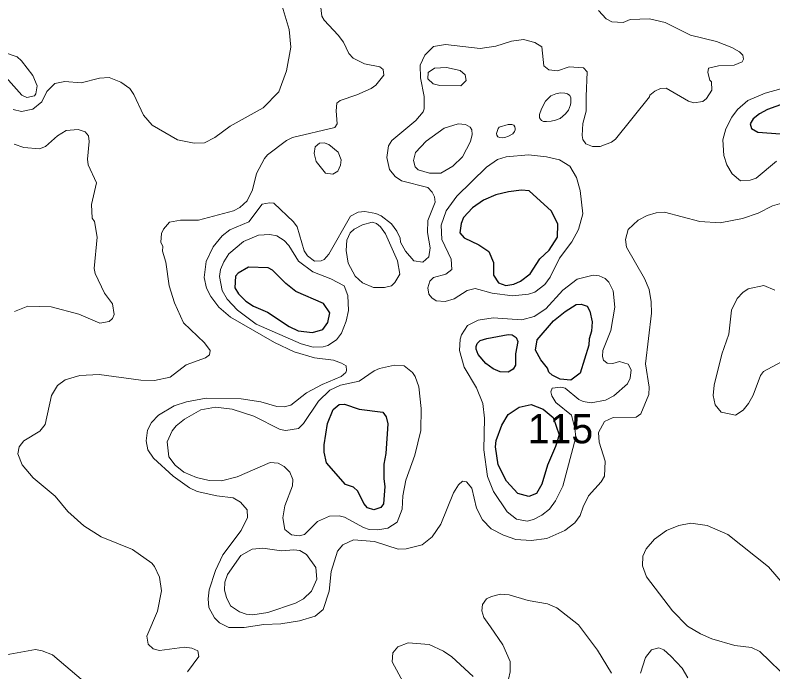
# Model space of a CAD drawing. Extents: x 673.6 to 698.9, y 7012 to 7040.1.
# Drawn here: x 682.608 to 684.675, y 7029.641 to 7031.434 of the extents above; entities that cross this region are included whole.
import ezdxf

# ---------------------------------------------------------------- set-up
doc = ezdxf.new("R2010")
doc.units = 0
doc.header["$LTSCALE"] = 0.032
doc.layers.add('1', color=7, linetype='Continuous', lineweight=25)
doc.layers.add('2', color=7, linetype='Continuous', lineweight=13)
doc.layers.add('21', color=7, linetype='Continuous')

msp = doc.modelspace()

# ---------------------------------------------------------------- linework, layer by layer
at = {"layer": '1'}
msp.add_lwpolyline([(684.7869, 7031.2225), (684.6612, 7031.1768), (684.6387, 7031.1647), (684.6215, 7031.1512), (684.6137, 7031.1377), (684.6176, 7031.1249), (684.6346, 7031.1151), (684.7212, 7031.109)], dxfattribs=at)
for points in [[(684.071, 7030.8996), (684.0106, 7030.9552), (683.9898, 7030.9562), (683.9537, 7030.9521), (683.9195, 7030.9439), (683.886, 7030.9297), (683.8561, 7030.908), (683.8311, 7030.8818), (683.8246, 7030.8655), (683.8215, 7030.8404), (683.8328, 7030.8268), (683.8731, 7030.8074), (683.9003, 7030.7892), (683.9132, 7030.7594), (683.9136, 7030.7241), (683.9265, 7030.7039), (683.947, 7030.6966), (683.9687, 7030.6995), (683.9872, 7030.7085), (684.0136, 7030.7278), (684.0395, 7030.7688), (684.0652, 7030.7924), (684.0876, 7030.828), (684.0885, 7030.8633)], [(683.374, 7030.6801), (683.3465, 7030.7013), (683.3102, 7030.7384), (683.2987, 7030.7449), (683.2443, 7030.7467), (683.2163, 7030.7303), (683.2091, 7030.7216), (683.2078, 7030.6896), (683.2171, 7030.6737), (683.2372, 7030.6535), (683.2583, 7030.6399), (683.2967, 7030.6232), (683.3556, 7030.5841), (683.38, 7030.5728), (683.4191, 7030.5676), (683.4471, 7030.5765), (683.4615, 7030.595), (683.4663, 7030.6217), (683.4491, 7030.6467)], [(684.1743, 7030.5505), (684.1735, 7030.5335), (684.1498, 7030.4569), (684.1242, 7030.4377), (684.095, 7030.441), (684.0729, 7030.4517), (684.0646, 7030.4594), (684.0606, 7030.4702), (684.0421, 7030.4937), (684.0278, 7030.5196), (684.0325, 7030.5482), (684.0773, 7030.5998), (684.1088, 7030.6255), (684.1385, 7030.644), (684.1525, 7030.6454), (684.1689, 7030.6403), (684.1763, 7030.6258), (684.1828, 7030.597), (684.1804, 7030.5716)], [(683.9535, 7030.4594), (683.9317, 7030.4605), (683.9123, 7030.4692), (683.8923, 7030.4835), (683.8717, 7030.5081), (683.8658, 7030.5226), (683.8661, 7030.5297), (683.8686, 7030.5377), (683.8771, 7030.5458), (683.8949, 7030.5512), (683.9535, 7030.5626), (683.9641, 7030.5616), (683.9746, 7030.5541), (683.9799, 7030.5433), (683.9736, 7030.5099), (683.973, 7030.4792), (683.9668, 7030.4677)], [(683.6197, 7030.2377), (683.6143, 7030.2088), (683.6135, 7030.1686), (683.6167, 7030.1476), (683.6132, 7030.1005), (683.6054, 7030.0906), (683.5871, 7030.084), (683.5697, 7030.0895), (683.5592, 7030.1009), (683.5432, 7030.1352), (683.5308, 7030.1454), (683.5095, 7030.1528), (683.4576, 7030.2122), (683.4508, 7030.2409), (683.4509, 7030.2609), (683.46, 7030.3194), (683.4753, 7030.3575), (683.4919, 7030.371), (683.5066, 7030.3726), (683.5465, 7030.3587), (683.6115, 7030.3506), (683.62, 7030.3374), (683.6249, 7030.3185)], [(684.092, 7030.2883), (684.0825, 7030.2567), (684.0606, 7030.2054), (684.0452, 7030.1535), (684.0303, 7030.1283), (684.0092, 7030.1198), (683.9794, 7030.1284), (683.949, 7030.1621), (683.9259, 7030.2064), (683.9183, 7030.2559), (683.9203, 7030.2734), (683.9355, 7030.3149), (683.9533, 7030.3443), (683.9833, 7030.3645), (684.0161, 7030.3716), (684.049, 7030.3587), (684.0756, 7030.3362)]]:
    msp.add_lwpolyline(points, close=True, dxfattribs=at)
at = {"layer": '2'}
for points in [[(683.0293, 7030.869), (683.0593, 7030.8748), (683.108, 7030.8749), (683.2035, 7030.9001), (683.2213, 7030.9089), (683.241, 7030.9272), (683.2559, 7030.9575), (683.2666, 7031.0017), (683.2879, 7031.043), (683.2963, 7031.053), (683.3484, 7031.0925), (683.3643, 7031.1001), (683.48, 7031.1279), (683.4869, 7031.1378), (683.4837, 7031.1728), (683.4855, 7031.1937), (683.4952, 7031.2018), (683.5402, 7031.2169), (683.5794, 7031.2343), (683.5924, 7031.2433), (683.6141, 7031.2708), (683.6117, 7031.2864), (683.6028, 7031.2929), (683.5616, 7031.3011), (683.5299, 7031.3174), (683.5183, 7031.33), (683.5035, 7031.3602), (683.4894, 7031.3802), (683.4512, 7031.4207), (683.4451, 7031.4316), (683.4384, 7031.4858)], [(683.3366, 7031.4588), (683.3554, 7031.395), (683.3603, 7031.3473), (683.3482, 7031.2823), (683.3274, 7031.2249), (683.2848, 7031.1812), (683.1943, 7031.1314), (683.1527, 7031.1005), (683.1246, 7031.0858), (683.0963, 7031.0845), (683.0505, 7031.094), (682.9818, 7031.1342), (682.9581, 7031.161), (682.9322, 7031.2175), (682.9212, 7031.2341), (682.896, 7031.2512), (682.864, 7031.2643), (682.8381, 7031.2628), (682.788, 7031.2499), (682.7437, 7031.2536), (682.7162, 7031.2476), (682.6947, 7031.2259), (682.6807, 7031.1979), (682.6561, 7031.1773), (682.6256, 7031.1715), (682.6021, 7031.1767)], [(684.1999, 7031.447), (684.2202, 7031.4245), (684.2363, 7031.4162), (684.2667, 7031.414), (684.286, 7031.4221), (684.339, 7031.4245), (684.3814, 7031.4143), (684.4505, 7031.3796), (684.522, 7031.3622)], [(684.5921, 7031.3072), (684.5699, 7031.2983), (684.5272, 7031.2964), (684.4996, 7031.2899), (684.498, 7031.2775), (684.5033, 7031.2567), (684.5077, 7031.2519), (684.5092, 7031.2294), (684.4946, 7031.2069), (684.4845, 7031.1987), (684.4594, 7031.1946), (684.4457, 7031.1992), (684.3843, 7031.2355), (684.3686, 7031.2339), (684.3531, 7031.2273), (684.3394, 7031.216), (684.3388, 7031.2115), (684.2459, 7031.0957), (684.2352, 7031.0875), (684.2039, 7031.0754), (684.1837, 7031.0762), (684.1654, 7031.0831), (684.1574, 7031.0945), (684.1551, 7031.1054), (684.1574, 7031.1383), (684.1665, 7031.1719), (684.1658, 7031.2122), (684.1688, 7031.2799), (684.1584, 7031.2904), (684.1197, 7031.2931), (684.0876, 7031.2826), (684.0645, 7031.2854), (684.0505, 7031.2964), (684.0455, 7031.3475), (684.0263, 7031.3595), (683.9951, 7031.3678), (683.9623, 7031.363), (683.9195, 7031.3499), (683.8771, 7031.3433), (683.7826, 7031.3539), (683.7491, 7031.3486), (683.7255, 7031.3254), (683.7129, 7031.298), (683.7142, 7031.263), (683.7244, 7031.2126), (683.7236, 7031.1785), (683.7209, 7031.1704), (683.7008, 7031.1471), (683.6359, 7031.092), (683.6265, 7031.0779), (683.6217, 7031.0461), (683.6297, 7031.0129), (683.6448, 7030.9943), (683.6619, 7030.9817), (683.7341, 7030.9636), (683.7457, 7030.9512), (683.7522, 7030.9384), (683.7539, 7030.9237), (683.7342, 7030.8737), (683.7335, 7030.8408), (683.74, 7030.7993), (683.7367, 7030.7748), (683.7208, 7030.7598), (683.6957, 7030.7639), (683.6734, 7030.7902), (683.6595, 7030.815), (683.6583, 7030.8253), (683.6496, 7030.8444), (683.6346, 7030.8643), (683.6063, 7030.8861), (683.5925, 7030.8928), (683.5622, 7030.8986), (683.544, 7030.8964), (683.5233, 7030.8856), (683.4637, 7030.7818), (683.4511, 7030.7676), (683.4431, 7030.7632), (683.4244, 7030.7624), (683.4058, 7030.7776), (683.3968, 7030.7907), (683.3771, 7030.8569), (683.3677, 7030.8702), (683.3142, 7030.9207), (683.3021, 7030.9217), (683.2822, 7030.918), (683.2452, 7030.8701), (683.1934, 7030.8481), (683.1724, 7030.8316), (683.1486, 7030.8023), (683.1295, 7030.7622), (683.1237, 7030.7184), (683.1301, 7030.6886), (683.1423, 7030.6663), (683.1639, 7030.6372), (683.1956, 7030.6096)], [(684.522, 7031.3622), (684.5638, 7031.3464), (684.5848, 7031.3342), (684.5935, 7031.3254), (684.5953, 7031.3146), (684.5921, 7031.3072)], [(684.5414, 7031.0509), (684.5388, 7031.0942), (684.5475, 7031.1237), (684.5631, 7031.1555), (684.5788, 7031.177), (684.6073, 7031.201), (684.6544, 7031.2218), (684.6974, 7031.2331)], [(682.6049, 7031.0825), (682.6313, 7031.0735), (682.6741, 7031.0695), (682.6904, 7031.0754), (682.723, 7031.1051), (682.7471, 7031.1197), (682.7802, 7031.1222), (682.799, 7031.1156), (682.8078, 7031.1051), (682.8097, 7031.0893), (682.8049, 7031.0416), (682.8072, 7031.0258), (682.8302, 7030.9762), (682.8163, 7030.9178), (682.8181, 7030.8801), (682.8247, 7030.8709), (682.8319, 7030.828), (682.8238, 7030.7429), (682.8259, 7030.7286), (682.8514, 7030.6758), (682.8731, 7030.6461), (682.8779, 7030.6172), (682.8738, 7030.6062), (682.8646, 7030.5981), (682.8389, 7030.5931), (682.7821, 7030.6183), (682.7059, 7030.6381), (682.6428, 7030.6399), (682.6063, 7030.6252)], [(684.6296, 7030.9897), (684.6134, 7030.9835), (684.5875, 7030.9818), (684.5648, 7031.0008), (684.5499, 7031.0259), (684.5414, 7031.0509)], [(684.6853, 7031.0361), (684.6296, 7030.9897)], [(684.38, 7030.8969), (684.4764, 7030.8712), (684.5317, 7030.8675), (684.5927, 7030.8788), (684.6351, 7030.8942), (684.6749, 7030.9141)], [(684.6749, 7030.9141), (684.7065, 7030.9225)], [(683.4984, 7030.4845), (683.5107, 7030.4768), (683.5124, 7030.4642), (683.5101, 7030.4585), (683.4974, 7030.448), (683.4461, 7030.4263), (683.403, 7030.4033), (683.3604, 7030.3697), (683.3423, 7030.3654), (683.3223, 7030.3662), (683.2782, 7030.3785), (683.2243, 7030.3867), (683.1287, 7030.3883), (683.0753, 7030.3791), (683.0419, 7030.3679), (682.9995, 7030.342), (682.9803, 7030.322), (682.969, 7030.3014), (682.9651, 7030.272), (682.9701, 7030.2479), (682.9854, 7030.2251), (683.0393, 7030.1753), (683.0839, 7030.1436), (683.1049, 7030.1339), (683.1583, 7030.1222), (683.2026, 7030.1163), (683.2226, 7030.1046), (683.2409, 7030.0838), (683.2421, 7030.0629), (683.2246, 7030.0273), (683.1748, 7029.9607), (683.1547, 7029.9184), (683.1374, 7029.8653), (683.1343, 7029.8407), (683.1362, 7029.8168), (683.1522, 7029.7892), (683.1654, 7029.7755), (683.1911, 7029.7622), (683.2329, 7029.7622), (683.2861, 7029.7704), (683.3329, 7029.7725), (683.3838, 7029.7803), (683.4268, 7029.7938), (683.4483, 7029.8118), (683.4648, 7029.862), (683.4704, 7029.9155), (683.4876, 7029.9712), (683.5023, 7029.9879), (683.5313, 7030.0022), (683.5885, 7029.9973), (683.6526, 7029.9767), (683.6751, 7029.9776), (683.7186, 7029.9882), (683.7457, 7030.0104), (683.7698, 7030.0443), (683.8043, 7030.1299), (683.8177, 7030.1519), (683.8283, 7030.1623), (683.8396, 7030.1604), (683.854, 7030.1428), (683.8665, 7030.0884), (683.8835, 7030.0566), (683.9066, 7030.032), (683.9407, 7030.0144), (683.9738, 7030.0029), (684.0158, 7029.9997), (684.0587, 7030.0055), (684.1078, 7030.0275), (684.135, 7030.0479), (684.15, 7030.0687), (684.1575, 7030.0917), (684.1727, 7030.122), (684.2066, 7030.1605), (684.2158, 7030.1754), (684.2182, 7030.217), (684.2019, 7030.2689), (684.1993, 7030.2953), (684.2161, 7030.3253), (684.24, 7030.3357), (684.3023, 7030.3369), (684.3151, 7030.3457), (684.3373, 7030.3987), (684.3382, 7030.4188), (684.3276, 7030.4821), (684.344, 7030.6206), (684.3432, 7030.6518), (684.3382, 7030.685), (684.3256, 7030.7151), (684.2761, 7030.801), (684.2734, 7030.8218), (684.2807, 7030.849), (684.3078, 7030.8748), (684.3322, 7030.8875), (684.3571, 7030.8946), (684.38, 7030.8969)], [(682.744, 7030.4385), (682.7842, 7030.4509), (682.8376, 7030.4534), (682.9504, 7030.4377), (682.9877, 7030.4369), (683.0309, 7030.4463), (683.0745, 7030.4795), (683.127, 7030.4987), (683.1383, 7030.507), (683.14, 7030.519), (683.1243, 7030.5398), (683.0671, 7030.5948), (683.0431, 7030.6488), (683.0283, 7030.6956), (683.0194, 7030.7603), (683.0104, 7030.7904), (683.0105, 7030.8032), (683.0054, 7030.8143), (683.0076, 7030.8384), (683.0129, 7030.8497), (683.0293, 7030.869)], [(684.6811, 7030.6836), (684.6506, 7030.6964), (684.6085, 7030.6869), (684.5933, 7030.677), (684.5777, 7030.6606), (684.5629, 7030.6287), (684.5552, 7030.5635), (684.5362, 7030.5088), (684.515, 7030.4241), (684.5128, 7030.3959), (684.5185, 7030.3706), (684.5341, 7030.3503), (684.5737, 7030.3425), (684.5946, 7030.3556), (684.6091, 7030.3742), (684.6216, 7030.3971), (684.642, 7030.4509), (684.6497, 7030.4615), (684.699, 7030.4878)], [(683.1956, 7030.6096), (683.3157, 7030.5406), (683.369, 7030.5154), (683.4247, 7030.4988), (683.4767, 7030.492), (683.4984, 7030.4845)], [(682.6315, 7030.2724), (682.675, 7030.2988), (682.6895, 7030.3164), (682.707, 7030.3957), (682.7236, 7030.4237), (682.744, 7030.4385)], [(683.0786, 7029.6413), (683.1087, 7029.6838), (683.106, 7029.6984), (683.0896, 7029.7062), (683.0702, 7029.7087), (683.002, 7029.6994), (682.9848, 7029.7043), (682.9708, 7029.7172), (682.9669, 7029.7393), (682.9962, 7029.8071), (683.007, 7029.8625), (683.002, 7029.8997), (682.9883, 7029.9287), (682.9807, 7029.938), (682.928, 7029.9754), (682.8423, 7030.0105), (682.7953, 7030.0405), (682.7517, 7030.0791), (682.7169, 7030.1213), (682.6573, 7030.171), (682.6272, 7030.2071), (682.6151, 7030.2364), (682.6184, 7030.256), (682.6315, 7030.2724)], [(684.7095, 7029.8751), (684.6637, 7029.928), (684.5522, 7030.0167), (684.496, 7030.0407), (684.4515, 7030.0474), (684.4188, 7030.0407), (684.385, 7030.027)], [(684.385, 7030.027), (684.3528, 7030.0036), (684.3295, 7029.9769), (684.3209, 7029.9577), (684.3201, 7029.931), (684.3305, 7029.9012)], [(684.3305, 7029.9012), (684.4019, 7029.8079), (684.4428, 7029.7659), (684.4776, 7029.7451), (684.5093, 7029.7315), (684.572, 7029.7136), (684.6171, 7029.7075), (684.6403, 7029.6974), (684.7223, 7029.6165)], [(684.2353, 7029.6375), (684.1967, 7029.7008), (684.1454, 7029.7694), (684.0857, 7029.816), (684.0604, 7029.8275), (684.0076, 7029.8363), (683.9562, 7029.8518), (683.9324, 7029.8534), (683.9076, 7029.8476), (683.8941, 7029.8405), (683.8831, 7029.8251), (683.8813, 7029.8078), (683.8871, 7029.7897), (683.9052, 7029.7647), (683.9391, 7029.715), (683.9585, 7029.6697), (683.9585, 7029.6415), (683.9539, 7029.6214)], [(683.8573, 7029.6287), (683.7994, 7029.6821), (683.7767, 7029.6982), (683.7378, 7029.716), (683.6801, 7029.7209), (683.6517, 7029.7097), (683.6389, 7029.6937), (683.6365, 7029.6689), (683.6664, 7029.6135)], [(682.5528, 7029.6825), (682.6632, 7029.7021), (682.6814, 7029.699), (682.7101, 7029.6878), (682.7941, 7029.6159), (682.805, 7029.5929), (682.8049, 7029.5662), (682.7875, 7029.526), (682.7576, 7029.4895), (682.7354, 7029.4513), (682.7277, 7029.4141), (682.734, 7029.3803), (682.7287, 7029.3463), (682.7155, 7029.3287), (682.6791, 7029.3061), (682.6304, 7029.2708), (682.5999, 7029.2654)], [(684.4434, 7029.6248), (684.4278, 7029.6512), (684.3974, 7029.6841), (684.3781, 7029.7013), (684.3645, 7029.707), (684.3439, 7029.702), (684.3283, 7029.6805), (684.3143, 7029.6378)]]:
    msp.add_lwpolyline(points, dxfattribs=at)
for points in [[(682.6255, 7031.3097), (682.6133, 7031.321), (682.5787, 7031.3325), (682.5623, 7031.3318), (682.5501, 7031.3207), (682.5525, 7031.2981), (682.6263, 7031.2162), (682.6402, 7031.2097), (682.6604, 7031.2138), (682.6643, 7031.2192), (682.6684, 7031.241), (682.6565, 7031.2695)], [(683.7666, 7031.2421), (683.8237, 7031.2416), (683.839, 7031.2557), (683.8359, 7031.2719), (683.8223, 7031.2834), (683.7851, 7031.2914), (683.7522, 7031.29), (683.7353, 7031.2778), (683.7343, 7031.2606), (683.7489, 7031.2468)], [(684.039, 7031.163), (684.039, 7031.1543), (684.0441, 7031.147), (684.0494, 7031.1443), (684.0578, 7031.1439), (684.0702, 7031.1449), (684.0826, 7031.1473), (684.095, 7031.1523), (684.1098, 7031.1654), (684.1178, 7031.1751), (684.1232, 7031.1892), (684.1242, 7031.1962), (684.1242, 7031.2086), (684.1215, 7031.2147), (684.1155, 7031.2197), (684.1074, 7031.2217), (684.096, 7031.2221), (684.0836, 7031.2197), (684.0695, 7031.2137), (684.0548, 7031.1993), (684.0441, 7031.1788)], [(683.7787, 7031.1262), (683.8172, 7031.1378), (683.8367, 7031.1362), (683.8499, 7031.1289), (683.8542, 7031.1211), (683.855, 7031.109), (683.8507, 7031.0891), (683.829, 7031.0478), (683.8025, 7031.022), (683.7694, 7031.0032), (683.7382, 7031.0027), (683.7076, 7031.0123), (683.6994, 7031.0205), (683.695, 7031.0377), (683.7004, 7031.0594), (683.729, 7031.09)], [(683.9381, 7031.1312), (683.929, 7031.1282), (683.926, 7031.1245), (683.923, 7031.1171), (683.9217, 7031.1111), (683.922, 7031.1064), (683.9247, 7031.1024), (683.9304, 7031.1003), (683.9371, 7031.0993), (683.9445, 7031.1003), (683.9545, 7031.1044), (683.9659, 7031.1107), (683.9703, 7031.1168), (683.9723, 7031.1215), (683.972, 7031.1248), (683.971, 7031.1295), (683.9686, 7031.1339), (683.9659, 7031.1349), (683.9632, 7031.1356), (683.9535, 7031.1356), (683.9445, 7031.1335)], [(683.4896, 7031.0606), (683.464, 7031.081), (683.4515, 7031.0859), (683.438, 7031.0851), (683.4262, 7031.0747), (683.4237, 7031.0565), (683.4291, 7031.0352), (683.4552, 7031.0031), (683.4748, 7031.0006), (683.4885, 7031.0082), (683.4958, 7031.0249), (683.4977, 7031.0395)], [(683.7814, 7030.6522), (683.8061, 7030.6601), (683.8416, 7030.6824), (683.8633, 7030.6883), (683.91, 7030.6758), (683.9647, 7030.6678), (684.0083, 7030.6724), (684.0264, 7030.6777), (684.0536, 7030.6987), (684.0678, 7030.7189), (684.093, 7030.7712), (684.1272, 7030.8151), (684.1455, 7030.8489), (684.1565, 7030.8918), (684.1497, 7030.9561), (684.1401, 7030.991), (684.1218, 7031.0222), (684.0934, 7031.0391), (684.0576, 7031.0474), (684.0087, 7031.0532), (683.9475, 7031.0475), (683.9245, 7031.0402), (683.8937, 7031.0194), (683.8134, 7030.9398), (683.7837, 7030.9006), (683.7708, 7030.8607), (683.772, 7030.8215), (683.7973, 7030.768), (683.7992, 7030.7404), (683.7832, 7030.727), (683.7497, 7030.7177), (683.7391, 7030.7077), (683.7343, 7030.6899), (683.7366, 7030.6725), (683.7446, 7030.6625), (683.7568, 7030.6547)], [(683.644, 7030.7041), (683.6577, 7030.7274), (683.6512, 7030.7639), (683.6184, 7030.8378), (683.6049, 7030.8561), (683.594, 7030.8652), (683.5823, 7030.869), (683.5556, 7030.8615), (683.5334, 7030.8497), (683.522, 7030.8399), (683.5134, 7030.8203), (683.5115, 7030.7921), (683.517, 7030.7577), (683.5357, 7030.7219), (683.5554, 7030.7032), (683.5856, 7030.6908), (683.6154, 7030.6908), (683.6349, 7030.6957)], [(683.4985, 7030.5665), (683.5114, 7030.5992), (683.5173, 7030.6284), (683.5155, 7030.6694), (683.5057, 7030.6956), (683.4692, 7030.7145), (683.4199, 7030.7333), (683.3815, 7030.7626), (683.3544, 7030.8053), (683.3423, 7030.8188), (683.3224, 7030.832), (683.3025, 7030.8353), (683.2716, 7030.8337), (683.2306, 7030.8165), (683.1914, 7030.7823), (683.1773, 7030.7609), (683.1684, 7030.7404), (683.1657, 7030.7207), (683.1728, 7030.6829), (683.1861, 7030.6586), (683.2147, 7030.6285), (683.2657, 7030.5904), (683.3886, 7030.537), (683.4207, 7030.5279), (683.448, 7030.5288), (683.4607, 7030.5329), (683.4844, 7030.5479)], [(684.1088, 7030.4162), (684.0966, 7030.4186), (684.0729, 7030.4161), (684.0696, 7030.4059), (684.0722, 7030.3953), (684.0833, 7030.3773), (684.1261, 7030.3421), (684.1353, 7030.3063), (684.1376, 7030.2826), (684.1021, 7030.1482), (684.0822, 7030.1088), (684.0657, 7030.0855), (684.0452, 7030.0695), (684.0222, 7030.0577), (684.0051, 7030.0531), (683.9764, 7030.0585), (683.9501, 7030.0781), (683.9131, 7030.1335), (683.8965, 7030.1744), (683.8867, 7030.248), (683.8887, 7030.3337), (683.8839, 7030.3741), (683.8669, 7030.4165), (683.8329, 7030.4733), (683.8206, 7030.5187), (683.8222, 7030.5499), (683.8257, 7030.562), (683.8425, 7030.5869), (683.8709, 7030.602), (683.9121, 7030.6078), (683.9902, 7030.6021), (684.024, 7030.6117), (684.0562, 7030.6329), (684.1027, 7030.6836), (684.1417, 7030.714), (684.1854, 7030.7244), (684.2018, 7030.7228), (684.218, 7030.7155), (684.2277, 7030.7057), (684.2396, 7030.6817), (684.2445, 7030.637), (684.2331, 7030.5736), (684.2116, 7030.5188), (684.2103, 7030.5021), (684.2135, 7030.4922), (684.2236, 7030.4845), (684.2388, 7030.4837), (684.2568, 7030.4886), (684.2808, 7030.4817), (684.2888, 7030.4661), (684.2858, 7030.4435), (684.2789, 7030.428), (684.2419, 7030.3951), (684.219, 7030.3835), (684.18, 7030.3761), (684.1577, 7030.3797), (684.1458, 7030.3854)], [(683.6427, 7030.4787), (683.6693, 7030.4771), (683.6923, 7030.4588), (683.6998, 7030.448), (683.7098, 7030.4198), (683.7161, 7030.3603), (683.7145, 7030.3005), (683.6982, 7030.2333), (683.674, 7030.1647), (683.6661, 7030.1216), (683.6637, 7030.0858), (683.6503, 7030.05), (683.6245, 7030.0341), (683.5975, 7030.0296), (683.574, 7030.0303), (683.5589, 7030.0352), (683.5062, 7030.0636), (683.4918, 7030.067), (683.4656, 7030.0662), (683.4329, 7030.052), (683.3979, 7030.0168), (683.3828, 7030.0129), (683.3616, 7030.0153), (683.3441, 7030.0299), (683.3381, 7030.0617), (683.3437, 7030.0945), (683.3649, 7030.1494), (683.3653, 7030.1662), (683.3573, 7030.1867), (683.3421, 7030.2025), (683.3252, 7030.211), (683.3035, 7030.2127), (683.2135, 7030.1738), (683.171, 7030.1633), (683.1374, 7030.1641), (683.103, 7030.172), (683.0682, 7030.187), (683.0446, 7030.2062), (683.0275, 7030.2286), (683.0225, 7030.2697), (683.0361, 7030.2994), (683.047, 7030.3133), (683.0697, 7030.3314), (683.1147, 7030.3571), (683.1542, 7030.3637), (683.1997, 7030.3587), (683.259, 7030.3395), (683.3311, 7030.3028), (683.3461, 7030.3005), (683.3807, 7030.3058), (683.3946, 7030.3191), (683.4361, 7030.3801), (683.4665, 7030.4104), (683.4958, 7030.4241), (683.5465, 7030.4348), (683.5872, 7030.4631), (683.6019, 7030.4697)], [(683.1843, 7029.8443), (683.1796, 7029.8642), (683.1805, 7029.8867), (683.1875, 7029.907), (683.2235, 7029.9589), (683.2543, 7029.9762), (683.2835, 7029.9791), (683.3346, 7029.9718), (683.3679, 7029.975), (683.3849, 7029.9728), (683.4033, 7029.9616), (683.4284, 7029.9264), (683.431, 7029.8946), (683.417, 7029.8617), (683.3943, 7029.8411), (683.3732, 7029.8286), (683.2971, 7029.8034), (683.2563, 7029.7975), (683.2382, 7029.7991), (683.2204, 7029.8051), (683.1952, 7029.8215)]]:
    msp.add_lwpolyline(points, close=True, dxfattribs=at)

# ---------------------------------------------------------------- texts
at = {"layer": '21'}
msp.add_text('115', height=0.08, dxfattribs=at).set_placement((684.0066, 7030.2654))

doc.saveas('drawing.dxf')
